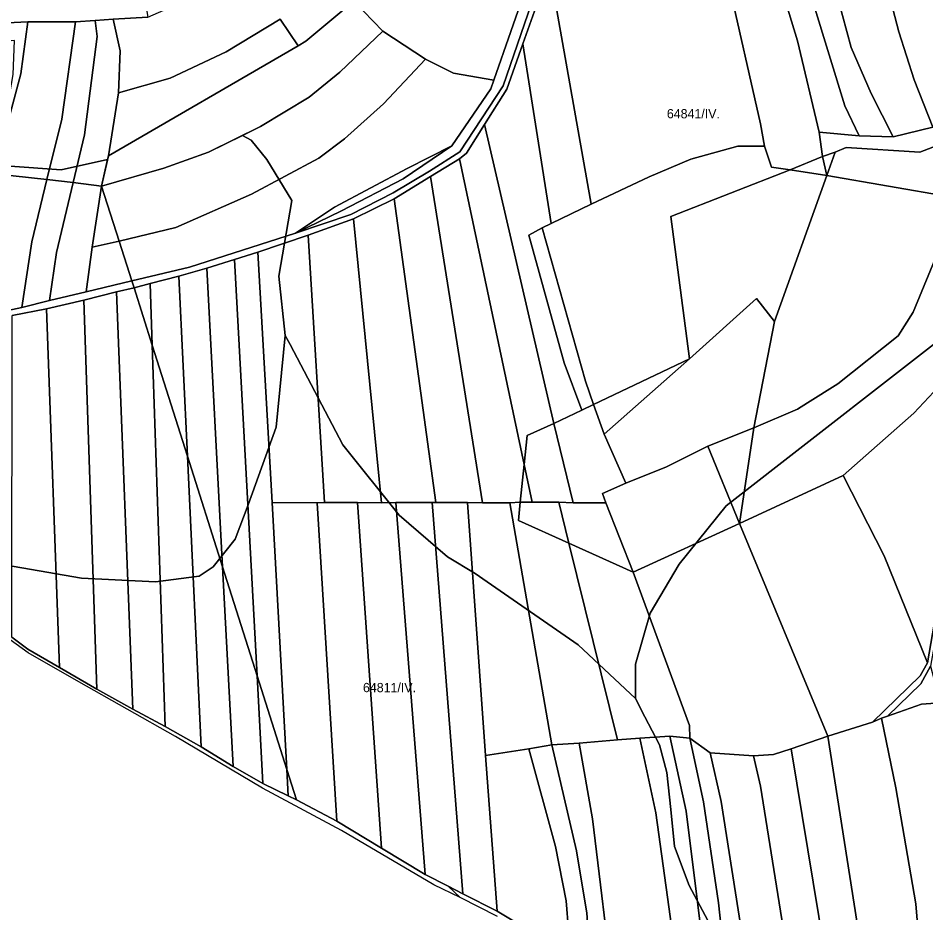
# Model space of a CAD drawing. Extents: x -521261 to -517465, y -1182764 to -1179456.
# Drawn here: x -520253.2 to -519763.3, y -1181970.8 to -1181487.6 of the extents above; entities that cross this region are included whole.
import ezdxf

# ---------------------------------------------------------------- set-up
doc = ezdxf.new("R2010")
doc.units = 0
for name, color, linetype in [('95560013', 7, 'Continuous'), ('95610013', 7, 'Continuous'), ('95620013', 7, 'Continuous'), ('95640013', 7, 'Continuous'), ('95660013', 7, 'Continuous')]:
    doc.layers.add(name, color=color, linetype=linetype)

msp = doc.modelspace()

# ---------------------------------------------------------------- linework, layer by layer
at = {"layer": '95560013'}
for points in [[(-519802.77, -1181378.03), (-519738.77, -1181350.12), (-519717.09, -1181452.91), (-519704.33, -1181495.42), (-519696.97, -1181527.88), (-519734.21, -1181538), (-519747.84, -1181543.58), (-519759.56, -1181546.55), (-519769.64, -1181520.91), (-519777.88, -1181495.02), (-519785.24, -1181466.55)], [(-519806.49, -1181379.47), (-519802.77, -1181378.03), (-519785.24, -1181466.55), (-519777.88, -1181495.02), (-519769.64, -1181520.91), (-519759.56, -1181546.55), (-519780.96, -1181551.7), (-519792.84, -1181528.25), (-519803.56, -1181503.4), (-519810.65, -1181477.32), (-519827.57, -1181391.18)], [(-519843.39, -1181398.48), (-519827.57, -1181391.18), (-519810.65, -1181477.32), (-519803.56, -1181503.4), (-519792.84, -1181528.25), (-519780.96, -1181551.7), (-519799.35, -1181551.07), (-519806.94, -1181535.03), (-519823.96, -1181479.91)], [(-519858.26, -1181404.56), (-519843.39, -1181398.48), (-519823.96, -1181479.91), (-519806.94, -1181535.03), (-519799.35, -1181551.07), (-519820.94, -1181549.11), (-519832.54, -1181499.93), (-519840.21, -1181474.26), (-519847.83, -1181440.64)], [(-519858.26, -1181404.56), (-519847.83, -1181440.64), (-519840.21, -1181474.26), (-519832.54, -1181499.93), (-519820.94, -1181549.11), (-519819.03, -1181562.34), (-519836.49, -1181569.45), (-519846.63, -1181568), (-519850.41, -1181556.71), (-519852.44, -1181544.73), (-519869.95, -1181467.47), (-519881.55, -1181422.98), (-519881.06, -1181420.17), (-519875.01, -1181415.68)], [(-520059.93, -1181422.38), (-520039.97, -1181441.63), (-520028.29, -1181450.94), (-520013.39, -1181460.97), (-520008.07, -1181463.33), (-519978.05, -1181468.4), (-519996.47, -1181521.04), (-520018.3, -1181517.23), (-520033.36, -1181509.68), (-520056.39, -1181494.56), (-520072.1, -1181478.37), (-520080.04, -1181470.38), (-520096.25, -1181448.83)], [(-519881.06, -1181420.17), (-519881.55, -1181422.98), (-519869.95, -1181467.47), (-519852.44, -1181544.73), (-519850.41, -1181556.71), (-519864.72, -1181556.65), (-519890.05, -1181563.82), (-519912.71, -1181573.25), (-519943.88, -1181587.97), (-519966.4, -1181460.95), (-519963.8, -1181454), (-519955.99, -1181466.92), (-519925.87, -1181445.17), (-519905.49, -1181435.85), (-519894.06, -1181430.89)], [(-519968.45, -1181457.09), (-519991.41, -1181524.14), (-520014.78, -1181559.72), (-520031.11, -1181570.27), (-520050.83, -1181581.91), (-520073.58, -1181593.67), (-520103.45, -1181603.73), (-520078.6, -1181591.68), (-520045.34, -1181574.36), (-520019.1, -1181556.48), (-519998.04, -1181525.72), (-519996.47, -1181521.04), (-519978.05, -1181468.4), (-519969.29, -1181444.31)], [(-519980.74, -1181501.54), (-519966.4, -1181460.95), (-519943.88, -1181587.97), (-519965.56, -1181598.45)], [(-520033.36, -1181509.68), (-520056.01, -1181533.94), (-520077.03, -1181552.84), (-520090.87, -1181563.28), (-520127.26, -1181582.57), (-520168.07, -1181600.73), (-520198.61, -1181607.97), (-520208.16, -1181578.29), (-520174.55, -1181568.61), (-520150.55, -1181560.01), (-520122.34, -1181546.18), (-520096.12, -1181530.34), (-520079.5, -1181516.84), (-520056.39, -1181494.56)], [(-519980.74, -1181501.54), (-519965.56, -1181598.45), (-519970.37, -1181600.93), (-519977.56, -1181604.73), (-519958.44, -1181673.73), (-519948.91, -1181699.36), (-519964.15, -1181706.5), (-520001.46, -1181545.08), (-519989.52, -1181525.94)], [(-520018.3, -1181517.23), (-519996.47, -1181521.04), (-519998.04, -1181525.72), (-520019.1, -1181556.48), (-520043.24, -1181568.73), (-520082.51, -1181589.75), (-520103.45, -1181603.73), (-520160.8, -1181622.11), (-520191.76, -1181629.43), (-520198.61, -1181607.97), (-520168.07, -1181600.73), (-520127.26, -1181582.57), (-520090.87, -1181563.28), (-520077.03, -1181552.84), (-520056.01, -1181533.94), (-520033.36, -1181509.68)], [(-519680.38, -1181522.18), (-519678.62, -1181526.13), (-519766.59, -1181560.03), (-519806.34, -1181557.48), (-519812.18, -1181559.97), (-519819.03, -1181562.34), (-519820.94, -1181549.11), (-519799.35, -1181551.07), (-519780.96, -1181551.7), (-519759.56, -1181546.55), (-519747.84, -1181543.58), (-519734.21, -1181538), (-519696.97, -1181527.88)], [(-520001.46, -1181545.08), (-519964.15, -1181706.5), (-519978.55, -1181713), (-519980.12, -1181728.65), (-520015.08, -1181563.53), (-520011.22, -1181560.49)], [(-520043.24, -1181568.73), (-520019.1, -1181556.48), (-520045.34, -1181574.36), (-520078.6, -1181591.68), (-520103.45, -1181603.73), (-520082.51, -1181589.75)], [(-519864.72, -1181556.65), (-519850.41, -1181556.71), (-519846.63, -1181568), (-519836.49, -1181569.45), (-519900.98, -1181594.75), (-519890.89, -1181671.5), (-519942.73, -1181696.28), (-519946.93, -1181683.67), (-519970.37, -1181600.93), (-519965.56, -1181598.45), (-519943.88, -1181587.97), (-519912.71, -1181573.25), (-519890.05, -1181563.82)], [(-520015.08, -1181563.53), (-519980.12, -1181728.65), (-519982.16, -1181749.05), (-519987.85, -1181749.27), (-520002.58, -1181749.27), (-520030.67, -1181573.12)], [(-520266.02, -1181571.63), (-520237.7, -1181574.77), (-520245.8, -1181608.4), (-520251.25, -1181643.84), (-520278.33, -1181649.59), (-520273.4, -1181608.7)], [(-520030.67, -1181573.12), (-520002.58, -1181749.27), (-520010.68, -1181749.17), (-520027.82, -1181749.25), (-520050.24, -1181585.12)], [(-520223.53, -1181576.38), (-520232.46, -1181614.19), (-520236.34, -1181640.1), (-520251.25, -1181643.84), (-520245.8, -1181608.4), (-520237.7, -1181574.77)], [(-520208.16, -1181578.29), (-520213.34, -1181611.3), (-520216.46, -1181635.34), (-520236.34, -1181640.1), (-520232.46, -1181614.19), (-520223.53, -1181576.38)], [(-520208.16, -1181578.29), (-520198.61, -1181607.97), (-520213.34, -1181611.3)], [(-520050.24, -1181585.12), (-520027.82, -1181749.25), (-520029.79, -1181749.26), (-520049.27, -1181749.25), (-520057.18, -1181749.29), (-520072.14, -1181596.05)], [(-520072.14, -1181596.05), (-520057.18, -1181749.29), (-520070.02, -1181749.25), (-520087.92, -1181749.25), (-520096.66, -1181604.88)], [(-519977.56, -1181604.73), (-519970.37, -1181600.93), (-519946.93, -1181683.67), (-519942.73, -1181696.28), (-519948.91, -1181699.36), (-519958.44, -1181673.73)], [(-520213.34, -1181611.3), (-520198.61, -1181607.97), (-520191.76, -1181629.43), (-520216.46, -1181635.34)], [(-520096.66, -1181604.88), (-520087.92, -1181749.25), (-520091.87, -1181749.27), (-520116.07, -1181749.24), (-520123.89, -1181613.91)], [(-520151.43, -1181622.71), (-520136.4, -1181617.98), (-520124.25, -1181842.77), (-520142.87, -1181783.97)], [(-520136.4, -1181617.98), (-520123.89, -1181613.91), (-520116.07, -1181749.24), (-520108.22, -1181893.38), (-520124.25, -1181842.77)], [(-520166.47, -1181626.99), (-520151.43, -1181622.71), (-520142.87, -1181783.97), (-520161.84, -1181724.09)], [(-520181.94, -1181630.91), (-520166.47, -1181626.99), (-520161.84, -1181724.09), (-520180.81, -1181664.23)], [(-520181.94, -1181630.91), (-520180.81, -1181664.23), (-520190.65, -1181633.19)], [(-520217.8, -1181639.98), (-520200.16, -1181635.38), (-520191.24, -1181860.79), (-520210.74, -1181849.98)], [(-520200.16, -1181635.38), (-520190.65, -1181633.19), (-520180.81, -1181664.23), (-520173.82, -1181870.19), (-520191.24, -1181860.79)], [(-520237.89, -1181644.57), (-520217.8, -1181639.98), (-520210.74, -1181849.98), (-520230.95, -1181838.28)], [(-520256.52, -1181648.14), (-520237.89, -1181644.57), (-520230.95, -1181838.28), (-520247.99, -1181828.33), (-520256.67, -1181821.86)], [(-519679.91, -1181647.56), (-519693.3, -1181688.1), (-519694.25, -1181691.29), (-519732.44, -1181714.35), (-519733.56, -1181715), (-519744.8, -1181747.67), (-519760.86, -1181837.52), (-519766.01, -1181847.11), (-519783.93, -1181864.52), (-519787.23, -1181865.65), (-519792.03, -1181867.82), (-519766.42, -1181842.85), (-519762.47, -1181835.83), (-519747.07, -1181747.06), (-519735.36, -1181712.66), (-519733.42, -1181711.55), (-519696.55, -1181689.51), (-519683.02, -1181648.68)], [(-520180.81, -1181664.23), (-520161.84, -1181724.09), (-520154.38, -1181881.07), (-520173.82, -1181870.19)], [(-519748.09, -1181677.97), (-519733.42, -1181711.55), (-519735.36, -1181712.66), (-519747.07, -1181747.06), (-519762.47, -1181835.83), (-519785.74, -1181777.95), (-519807.95, -1181734.53), (-519769.78, -1181700.98)], [(-520161.84, -1181724.09), (-520142.87, -1181783.97), (-520137.16, -1181891.69), (-520154.38, -1181881.07)], [(-519807.95, -1181734.53), (-519785.74, -1181777.95), (-519762.47, -1181835.83), (-519766.42, -1181842.85), (-519792.03, -1181867.82), (-519816.1, -1181875.42), (-519863.92, -1181760.51)], [(-520116.07, -1181749.24), (-520091.87, -1181749.27), (-520081.13, -1181921.33), (-520103.01, -1181909.83), (-520108.22, -1181893.38)], [(-520087.92, -1181749.25), (-520070.02, -1181749.25), (-520057.17, -1181935.79), (-520081.13, -1181921.33), (-520091.87, -1181749.27)], [(-520057.18, -1181749.29), (-520049.27, -1181749.25), (-520033.45, -1181950.01), (-520057.17, -1181935.79), (-520070.02, -1181749.25)], [(-520049.27, -1181749.25), (-520029.79, -1181749.26), (-520013.17, -1181960.59), (-520021.07, -1181956.38), (-520033.45, -1181950.01)], [(-520027.82, -1181749.25), (-520010.68, -1181749.17), (-520001.03, -1181885.73), (-519994.63, -1181969.85), (-520013.17, -1181960.59), (-520029.79, -1181749.26)], [(-520010.68, -1181749.17), (-520002.58, -1181749.27), (-519987.85, -1181749.27), (-519965.23, -1181880.12), (-519977.53, -1181882.16), (-520001.03, -1181885.73)], [(-519987.85, -1181749.27), (-519982.16, -1181749.05), (-519983.1, -1181758.9), (-519955.98, -1181771.12), (-519929.69, -1181877.39), (-519950.34, -1181879.12), (-519965.23, -1181880.12)], [(-519863.92, -1181760.51), (-519816.1, -1181875.42), (-519836.04, -1181882.28), (-519845.54, -1181885.36), (-519856.3, -1181885.93), (-519879.73, -1181884.43), (-519890.67, -1181876.54), (-519890.84, -1181869.64), (-519921.32, -1181786.75)], [(-519955.98, -1181771.12), (-519921.32, -1181786.75), (-519890.84, -1181869.64), (-519890.67, -1181876.54), (-519901.51, -1181875.35), (-519917.69, -1181876.52), (-519929.69, -1181877.39)], [(-520142.87, -1181783.97), (-520124.25, -1181842.77), (-520121.1, -1181900.92), (-520137.16, -1181891.69)], [(-519766.01, -1181847.11), (-519760.86, -1181837.52), (-519755.59, -1181857.41), (-519765.71, -1181858.12), (-519783.93, -1181864.52)], [(-520124.25, -1181842.77), (-520108.22, -1181893.38), (-520107.44, -1181907.56), (-520121.1, -1181900.92)], [(-519755.59, -1181857.41), (-519732.49, -1181855.46), (-519716.14, -1181990.99), (-519732.22, -1181989.26), (-519750.52, -1181989.15), (-519766.51, -1181992.23), (-519768.6, -1181965.95), (-519779.45, -1181903.21), (-519787.23, -1181865.65), (-519783.93, -1181864.52), (-519765.71, -1181858.12)], [(-519792.03, -1181867.82), (-519787.23, -1181865.65), (-519779.45, -1181903.21), (-519768.6, -1181965.95), (-519766.51, -1181992.23), (-519764.1, -1182025.47), (-519766.34, -1182080.33), (-519763.35, -1182088.59), (-519776, -1182086.02), (-519783.42, -1182084.3), (-519816.1, -1181875.42)], [(-519929.69, -1181877.39), (-519917.69, -1181876.52), (-519908.98, -1181916.85), (-519900.39, -1181979.22), (-519895.33, -1182040.48), (-519931.81, -1182013.55), (-519943.29, -1181920.06), (-519950.34, -1181879.12)], [(-519917.69, -1181876.52), (-519901.51, -1181875.35), (-519892.61, -1181915.95), (-519880.3, -1182015.66), (-519878.46, -1182053.14), (-519895.33, -1182040.48), (-519900.39, -1181979.22), (-519908.98, -1181916.85)], [(-519901.51, -1181875.35), (-519890.67, -1181876.54), (-519883.29, -1181910.85), (-519875.19, -1181965.41), (-519870.4, -1182010.47), (-519868.69, -1182060.16), (-519878.46, -1182053.14), (-519880.3, -1182015.66), (-519892.61, -1181915.95)], [(-519890.67, -1181876.54), (-519879.73, -1181884.43), (-519873.74, -1181910.59), (-519861.65, -1181987.47), (-519857.73, -1182070.93), (-519868.69, -1182060.16), (-519870.4, -1182010.47), (-519875.19, -1181965.41), (-519883.29, -1181910.85)], [(-519836.04, -1181882.28), (-519816.1, -1181875.42), (-519783.42, -1182084.3), (-519803.2, -1182080.84)], [(-520001.03, -1181885.73), (-519977.53, -1181882.16), (-519963.23, -1181935.04), (-519957.37, -1181964.28), (-519954.83, -1181995.98), (-519977.19, -1181980.37), (-519994.63, -1181969.85)], [(-519977.53, -1181882.16), (-519965.23, -1181880.12), (-519951.93, -1181937.3), (-519946.21, -1181970.89), (-519943.66, -1182004.75), (-519954.83, -1181995.98), (-519957.37, -1181964.28), (-519963.23, -1181935.04)], [(-519965.23, -1181880.12), (-519950.34, -1181879.12), (-519943.29, -1181920.06), (-519931.81, -1182013.55), (-519943.66, -1182004.75), (-519946.21, -1181970.89), (-519951.93, -1181937.3)], [(-519845.54, -1181885.36), (-519836.04, -1181882.28), (-519803.2, -1182080.84), (-519824.34, -1182079), (-519852.55, -1181902.33), (-519856.3, -1181885.93)], [(-519879.73, -1181884.43), (-519856.3, -1181885.93), (-519852.55, -1181902.33), (-519824.34, -1182079), (-519832.47, -1182077.97), (-519857.73, -1182070.93), (-519861.65, -1181987.47), (-519873.74, -1181910.59)], [(-520107.44, -1181907.56), (-520108.22, -1181893.38), (-520103.01, -1181909.83)]]:
    msp.add_lwpolyline(points, close=True, dxfattribs=at)
for points in [[(-519966.4, -1181460.95), (-519980.74, -1181501.54), (-519989.52, -1181525.94), (-520001.46, -1181545.08), (-520011.22, -1181560.49), (-520015.08, -1181563.53), (-520030.67, -1181573.12), (-520050.24, -1181585.12), (-520072.14, -1181596.05), (-520096.66, -1181604.88), (-520123.89, -1181613.91), (-520136.4, -1181617.98), (-520151.43, -1181622.71), (-520166.47, -1181626.99), (-520181.94, -1181630.91), (-520190.65, -1181633.19), (-520191.76, -1181629.43), (-520160.8, -1181622.11), (-520103.45, -1181603.73), (-520073.58, -1181593.67), (-520050.83, -1181581.91), (-520031.11, -1181570.27), (-520014.78, -1181559.72), (-519991.41, -1181524.14), (-519968.45, -1181457.09)], [(-520278.33, -1181649.59), (-520251.25, -1181643.84), (-520236.34, -1181640.1), (-520216.46, -1181635.34), (-520191.76, -1181629.43), (-520190.65, -1181633.19), (-520200.16, -1181635.38), (-520217.8, -1181639.98), (-520237.89, -1181644.57), (-520256.52, -1181648.14)], [(-519994.4, -1181972.81), (-520014.65, -1181962.59), (-520021.07, -1181956.38), (-520013.17, -1181960.59), (-519994.63, -1181969.85), (-519977.19, -1181980.37)]]:
    msp.add_lwpolyline(points, dxfattribs=at)
at = {"layer": '95610013'}
for points in [[(-520248.06, -1181489.62), (-520251.84, -1181517.59), (-520263.43, -1181560.87), (-520255.94, -1181517.97), (-520255.16, -1181499.72), (-520278.35, -1181501.97), (-520282.48, -1181502.26), (-520307.94, -1181498.71), (-520307.36, -1181492.97), (-520303.01, -1181492.71), (-520277.86, -1181490.96)], [(-520222.29, -1181489.55), (-520229.64, -1181542.18), (-520237.7, -1181574.77), (-520266.02, -1181571.63), (-520263.43, -1181560.87), (-520251.84, -1181517.59), (-520248.06, -1181489.62)], [(-520211.67, -1181488.9), (-520210.57, -1181497.51), (-520217.47, -1181550.66), (-520223.53, -1181576.38), (-520237.7, -1181574.77), (-520229.64, -1181542.18), (-520222.29, -1181489.55)], [(-520201.97, -1181488.21), (-520198.13, -1181505.28), (-520198.96, -1181527.88), (-520204.49, -1181561.93), (-520208.16, -1181578.29), (-520223.53, -1181576.38), (-520217.47, -1181550.66), (-520210.57, -1181497.51), (-520211.67, -1181488.9)], [(-519678.62, -1181526.13), (-519673.88, -1181539.64), (-519666.73, -1181552.31), (-519675.86, -1181551.28), (-519701.01, -1181560.52), (-519714.71, -1181563.35), (-519750.21, -1181584.11), (-519816.71, -1181572.59), (-519812.18, -1181559.97), (-519806.34, -1181557.48), (-519766.59, -1181560.03)], [(-519816.71, -1181572.59), (-519750.21, -1181584.11), (-519751.5, -1181601.06), (-519770.09, -1181646.33), (-519778.31, -1181659.21), (-519810.79, -1181685), (-519827.1, -1181695.28), (-519832.55, -1181698.75), (-519856.07, -1181708.81), (-519845.05, -1181651.51)], [(-519750.21, -1181584.11), (-519725.37, -1181578.38), (-519719.9, -1181605.52), (-519723.1, -1181623.37), (-519722.14, -1181630.1), (-519725.3, -1181640.16), (-519736.69, -1181666.21), (-519748.09, -1181677.97), (-519769.78, -1181700.98), (-519807.95, -1181734.53), (-519863.92, -1181760.51), (-519856.07, -1181708.81), (-519832.55, -1181698.75), (-519827.1, -1181695.28), (-519810.79, -1181685), (-519778.31, -1181659.21), (-519770.09, -1181646.33), (-519751.5, -1181601.06)]]:
    msp.add_lwpolyline(points, close=True, dxfattribs=at)
at = {"layer": '95620013'}
for points in [[(-520080.04, -1181470.38), (-520072.1, -1181478.37), (-520097.97, -1181500.05), (-520102.02, -1181502.48), (-520111.72, -1181488.08), (-520140.88, -1181505.85), (-520171.13, -1181520), (-520198.96, -1181527.88), (-520198.13, -1181505.28), (-520201.97, -1181488.21), (-520183.26, -1181487.11), (-520096.25, -1181448.83)], [(-520220.56, -1181464.03), (-520188.68, -1181456.43), (-520183.26, -1181487.11), (-520201.97, -1181488.21), (-520211.67, -1181488.9), (-520222.29, -1181489.55), (-520248.06, -1181489.62), (-520277.86, -1181490.96), (-520303.01, -1181492.71), (-520305.37, -1181477.77), (-520276.65, -1181475.26), (-520249.84, -1181470.67)], [(-520056.39, -1181494.56), (-520079.5, -1181516.84), (-520096.12, -1181530.34), (-520122.34, -1181546.18), (-520150.55, -1181560.01), (-520174.55, -1181568.61), (-520208.16, -1181578.29), (-520204.49, -1181561.93), (-520102.02, -1181502.48), (-520097.97, -1181500.05), (-520072.1, -1181478.37)], [(-520102.02, -1181502.48), (-520204.49, -1181561.93), (-520198.96, -1181527.88), (-520171.13, -1181520), (-520140.88, -1181505.85), (-520111.72, -1181488.08)]]:
    msp.add_lwpolyline(points, close=True, dxfattribs=at)
at = {"layer": '95640013'}
for points in [[(-519819.03, -1181562.34), (-519816.71, -1181572.59), (-519836.49, -1181569.45)], [(-519812.18, -1181559.97), (-519816.71, -1181572.59), (-519819.03, -1181562.34)], [(-519836.49, -1181569.45), (-519816.71, -1181572.59), (-519845.05, -1181651.51), (-519854.74, -1181638.96), (-519890.89, -1181671.5), (-519900.98, -1181594.75)], [(-519845.05, -1181651.51), (-519856.07, -1181708.81), (-519880.99, -1181718.72), (-519903.29, -1181729.92), (-519925.16, -1181738.78), (-519936.89, -1181712.29), (-519890.89, -1181671.5), (-519854.74, -1181638.96)], [(-519942.73, -1181696.28), (-519890.89, -1181671.5), (-519936.89, -1181712.29)], [(-519948.91, -1181699.36), (-519942.73, -1181696.28), (-519936.89, -1181712.29), (-519925.16, -1181738.78), (-519937.85, -1181744.26), (-519935.92, -1181749.28), (-519953.68, -1181749.27), (-519964.15, -1181706.5)], [(-519978.55, -1181713), (-519964.15, -1181706.5), (-519953.68, -1181749.27), (-519961.45, -1181748.98), (-519975.82, -1181748.91), (-519980.12, -1181728.65)], [(-519880.99, -1181718.72), (-519856.07, -1181708.81), (-519863.92, -1181760.51)], [(-519880.99, -1181718.72), (-519863.92, -1181760.51), (-519921.32, -1181786.75), (-519935.92, -1181749.28), (-519937.85, -1181744.26), (-519925.16, -1181738.78), (-519903.29, -1181729.92)], [(-519980.12, -1181728.65), (-519975.82, -1181748.91), (-519982.16, -1181749.05)], [(-519975.82, -1181748.91), (-519961.45, -1181748.98), (-519955.98, -1181771.12), (-519983.1, -1181758.9), (-519982.16, -1181749.05)], [(-519961.45, -1181748.98), (-519953.68, -1181749.27), (-519935.92, -1181749.28), (-519921.32, -1181786.75), (-519955.98, -1181771.12)]]:
    msp.add_lwpolyline(points, close=True, dxfattribs=at)
msp.add_lwpolyline([(-520256.67, -1181821.86), (-520247.99, -1181828.33), (-520230.95, -1181838.28), (-520210.74, -1181849.98), (-520191.24, -1181860.79), (-520173.82, -1181870.19), (-520154.38, -1181881.07), (-520137.16, -1181891.69), (-520121.1, -1181900.92), (-520107.44, -1181907.56), (-520103.01, -1181909.83), (-520081.13, -1181921.33), (-520057.17, -1181935.79), (-520033.45, -1181950.01), (-520021.07, -1181956.38), (-520014.65, -1181962.59), (-520028.82, -1181955.61), (-520078.63, -1181926.25), (-520121.36, -1181903.51), (-520168.26, -1181875.49), (-520220.41, -1181846.07), (-520247.74, -1181830.3), (-520273.94, -1181811.64)], dxfattribs=at)
at = {"layer": '95660013'}
for points in [[(-520305.37, -1181477.77), (-520303.01, -1181492.71), (-520277.86, -1181490.96), (-520248.06, -1181489.62), (-520222.29, -1181489.55), (-520211.67, -1181488.9), (-520201.97, -1181488.21), (-520198.13, -1181505.28), (-520198.96, -1181527.88), (-520204.49, -1181561.93), (-520204.95, -1181563.97), (-520205, -1181564), (-520230, -1181569.5), (-520257.5, -1181567.5), (-520280.5, -1181561), (-520296, -1181553), (-520306, -1181543.5), (-520323, -1181517), (-520328.5, -1181503.5), (-520333.5, -1181440.5)], [(-520072.1, -1181478.37), (-520056.39, -1181494.56), (-520079.5, -1181516.84), (-520096.12, -1181530.34), (-520122.34, -1181546.18), (-520132.11, -1181550.97), (-520150.55, -1181560.01), (-520174.55, -1181568.61), (-520208.16, -1181578.29), (-520204.95, -1181563.97), (-520204.49, -1181561.93), (-520198.96, -1181527.88), (-520198.13, -1181505.28), (-520201.97, -1181488.21), (-520211.67, -1181488.9), (-520222.29, -1181489.55), (-520248.06, -1181489.62), (-520277.86, -1181490.96), (-520303.01, -1181492.71), (-520305.37, -1181477.77)], [(-519735.5, -1181645.5), (-519871, -1181751), (-519896.5, -1181782.5), (-519912, -1181809), (-519920, -1181836.5), (-519920, -1181855), (-519951, -1181826), (-520000, -1181792.01), (-520006.5, -1181787.5), (-520021.5, -1181778.5), (-520047.5, -1181756), (-520078, -1181718), (-520106.41, -1181663.93), (-520109, -1181659), (-520112.5, -1181627), (-520105.5, -1181586), (-520119, -1181564), (-520127.5, -1181553.5), (-520132.11, -1181550.97), (-520122.34, -1181546.18), (-520096.12, -1181530.34), (-520079.5, -1181516.84), (-520056.39, -1181494.56), (-520072.1, -1181478.37)], [(-520257.5, -1181567.5), (-520230, -1181569.5), (-520205, -1181564), (-520204.95, -1181563.97), (-520208.16, -1181578.29), (-520174.55, -1181568.61), (-520150.55, -1181560.01), (-520132.11, -1181550.97), (-520127.5, -1181553.5), (-520119, -1181564), (-520105.5, -1181586), (-520112.5, -1181627), (-520109, -1181659), (-520114, -1181708.5), (-520129, -1181750.5), (-520136, -1181769), (-520148, -1181784), (-520155.5, -1181789), (-520179, -1181792), (-520219, -1181790), (-520306.5, -1181775)], [(-519881, -1181975), (-519891, -1181956), (-519899, -1181935), (-519901, -1181915), (-519903, -1181895), (-519907, -1181880), (-519915, -1181865), (-519920, -1181855), (-519920, -1181836.5), (-519912, -1181809), (-519896.5, -1181782.5), (-519871, -1181751), (-519735.5, -1181645.5)], [(-520306.5, -1181775), (-520219, -1181790), (-520179, -1181792), (-520155.5, -1181789), (-520148, -1181784), (-520136, -1181769), (-520129, -1181750.5), (-520114, -1181708.5), (-520109, -1181659), (-520106.41, -1181663.93), (-520078, -1181718), (-520047.5, -1181756), (-520021.5, -1181778.5), (-520006.5, -1181787.5), (-520000, -1181792.01), (-519951, -1181826), (-519920, -1181855), (-519915, -1181865), (-519907, -1181880), (-519903, -1181895), (-519901, -1181915), (-519899, -1181935), (-519891, -1181956), (-519881, -1181975)], [(-519994.4, -1181972.81), (-520014.65, -1181962.59), (-520028.82, -1181955.61), (-520078.63, -1181926.25), (-520121.36, -1181903.51), (-520168.26, -1181875.49), (-520220.41, -1181846.07), (-520247.74, -1181830.3), (-520273.94, -1181811.64)]]:
    msp.add_lwpolyline(points, dxfattribs=at)

# ---------------------------------------------------------------- texts
for s, p in [('64841/IV.', (-519903.06, -1181541.7)), ('64811/IV.', (-520067.09, -1181851.62))]:
    msp.add_text(s, height=5, rotation=360, dxfattribs=at).set_placement(p)

doc.saveas('drawing.dxf')
